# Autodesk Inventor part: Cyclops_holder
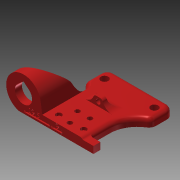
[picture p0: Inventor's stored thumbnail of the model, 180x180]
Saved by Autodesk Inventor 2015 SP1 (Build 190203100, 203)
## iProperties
Created: 2015-09
Part Number: Cyclops_holder
Material: Generic
Document SubType Name: Modeling
Designer: egor
Density: 1 g/cm^3
Appearance: Default
Author: egor
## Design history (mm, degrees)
sketch "Sketch1"
  geometry: L1 (-15, 26.5)-(15, 26.5); L2 (15, 26.5)-(15, -26.5); L3 (15, -26.5)-(-15, -26.5); L4 (-15, -26.5)-(-15, 26.5); L5 (15, -26.5)-(22, -26.5); L6 (22, -26.5)-(22, -21.5); L7 (22, -21.5)-(15, -21.5); L8 (15, -21.5)-(15, -26.5); L9 (15, 26.5)-(27, 26.5); L10 (27, 26.5)-(27, 10.5); L11 (27, 10.5)-(15, 10.5); L12 (15, 10.5)-(15, 26.5); L13 (-15, 26.5)-(-21, 26.5); L14 (-21, 26.5)-(-21, 10.5); L15 (-21, 10.5)-(-15, 10.5); L16 (-15, 10.5)-(-15, 26.5); C1 r 1.7 at (-4.5, -11.5); C2 r 1.7 at (4.5, -11.5); C3 r 1.7 at (0, -21.5); C4 r 2.7 at (-15, 18.5); C5 r 2.7 at (21, 18.5); 5 further points
  constraints: 32 end point, 8 parallel, 5 centre point, 4 horizontal, 4 horizontal alignment, 4 midpoint, 4 perpendicular, 3 equal radius, 2 vertical alignment, 1 coincident, 1 collinear
  dimensions: "d0" = 30 distance of L2.end L3.end; "d3" = 3.4 diameter of C3; "d6" = 9 distance of C2.centre C1.centre; "d7" = 4.5 horizontal distance of point (0, 0) C2.centre; "d8" = 10 vertical distance of C3.centre C2.centre; "d9" = 5 distance from line of L3 C3.centre; "d10" = 7 distance of L7.end L6.end; "d11" = 5 distance between parallel lines of L5 L7; "d12" = 16 distance of L9.end L10.end; "d14" = 5.4 diameter of C4; "d15" = 6 distance from line of L14 C4.centre; "d17" = 6 distance from line of L12 C5.centre; "d18" = 6 distance from line of L10 C5.centre; "d48" = 40 vertical distance of C3.centre C5.centre; "d110" = 30 distance from line of L2 C4.centre
extrude "Base" new body sketch "Sketch1" distance "d19" = 6; taper "d20" = 0 deg
sketch "Sketch2"
  geometry: L1 (0, 6)-(37, 6) reference; L2 (0, 0)-(0, 6) reference; L3 (0, 0)-(-17, 0); L4 (42, 0)-(-6, 0) reference; L5 (0, 6)-(-2.534, 6); L6 (0, 6)-(-1.129, 13.793); L7 (-13.5, 20.094)-(-17.485, 16.749); L8 (-13.5, 20.094)-(-9.515, 16.749); A1 r 12.5 centre (-13.5, 12) between (-10, 0) and (-17, 0); A2 r 6.2 centre (-13.5, 12) between (-17.485, 16.749) and (-9.515, 16.749); 1 further point
  constraints: 10 end point, 6 point on circle, 3 tangent, 2 centre point, 2 collinear, 1 coincident, 1 point on line, 1 vertical alignment
  dimensions: "d21" = 25 diameter of A1; "d23" = 12.4 diameter of A2; "d24" = 1 distance edge to line of A1 L2; "d25" = 6 distance from line of L1 A1.centre; "d28" = 100 deg angle of L8 L7
extrude "Sensor holder" join sketch "Sketch2" distance "d40" = 5; taper "d41" = 0 deg
fillet "Sensor enforcement" dims "d42" = 25
extrude "sensor hole" cut sketch "Sketch2" stored distance "d43" = 5; taper "d44" = 0 deg
sketch "Sketch3"
  geometry: L1 (-13.5, -1.954)-(-4.8, -6.977); L2 (-4.8, -6.977)-(-4.8, -17.023); L3 (-4.8, -17.023)-(-13.5, -22.046); L4 (-13.5, -22.046)-(-22.2, -17.023); L5 (-22.2, -17.023)-(-22.2, -6.977); L6 (-22.2, -6.977)-(-13.5, -1.954); A1 r 6.2 centre (-13.5, -12) between (-9.515, -16.749) and (-17.485, -16.749) reference; 2 further points
  constraints: 12 end point, 1 coincident, 13 other
  dimensions: "d45" = 17.4 distance between parallel lines of L2 L5
extrude "Sensor nut" cut sketch "Sketch3" stored distance "d46" = 0; taper "d47" = 0 deg; dims "d0" = 30, "d3" = 3.4, "d6" = 9, "d7" = 4.5, "d8" = 10, "d9" = 5, "d10" = 7, "d11" = 5, "d12" = 16, "d14" = 5.4, "d15" = 6, "d17" = 6, "d18" = 6, "d48" = 40, "d110" = 30
fillet "horizontal enforcement" dims "d49" = 20
sketch "Sketch4"
  geometry: L1 (-3, 1.9)-(3, 1.9); L2 (3, 1.9)-(3, -1.1); L3 (3, -1.1)-(-3, -1.1); L4 (-3, -1.1)-(-3, 1.9); C1 r 2 at (-9, -20.5); C2 r 2 at (9, -20.5); C3 r 1.7 at (0, -21.5) reference; 2 further points
  constraints: 8 end point, 2 centre point, 2 parallel, 1 equal radius, 1 horizontal, 1 horizontal alignment, 1 midpoint, 1 perpendicular, 1 vertical alignment
  dimensions: "d50" = 4 diameter of C1; "d51" = 18 distance of C2.centre C1.centre; "d54" = 1 vertical distance of C3.centre C2.centre; "d55" = 9 horizontal distance of C2.centre C3.centre (= 0.5 x d51); "d58" = 6 distance of L2.end L3.end; "d59" = 3 distance of L1.end L2.end; "d60" = 20.4 distance from line of L3 C3.centre
extrude "space for bolts" cut sketch "Sketch4" distance "d56" = 2; taper "d57" = 0 deg
extrude "upper fixator" join sketch "Sketch4" distance "d61" = 6; taper "d62" = 0 deg
fillet "upper fixator enforcement" dims "d63" = 7
sketch "Sketch7"
  geometry: L1 (0, 5)-(-6, 5) reference; L2 (-6, 0)-(-5, 0); L3 (-5, 0)-(-5, 5); L4 (-5, 5)-(-6, 5); L5 (-6, 5)-(-6, 0); 1 further point
  constraints: 8 end point, 2 parallel, 1 horizontal, 1 perpendicular, 1 point on line
  dimensions: "d72" = 1 distance of L4.end L3.end
extrude "arm for support" cut sketch "Sketch7" stored distance "d73" = 10; taper "d74" = 0 deg
fillet "Fillet9" dims "d90" = 5
fillet "Fillet10" dims "d91" = 3
fillet "Fillet11" dims "d92" = 2
sketch "Sketch5"
  geometry: L1 (-5.072, 0)-(31.928, 0) reference; C1 r 1.7 at (9.928, 3); 1 further point
  constraints: 1 centre point
  dimensions: "d64" = 3.4 diameter of C1; "d65" = 3 distance from line of L1 C1.centre
extrude "upper fixator hole" cut sketch "Sketch5" stored distance "d66" = 6; taper "d67" = 0 deg; dims "d0" = 30, "d3" = 3.4, "d6" = 9, "d7" = 4.5, "d8" = 10, "d9" = 5, "d10" = 7, "d11" = 5, "d12" = 16, "d14" = 5.4, "d15" = 6, "d17" = 6, "d18" = 6, "d48" = 40, "d110" = 30
sketch "Sketch9"
  geometry: C1 r 1.7 at (3.175, 2) reference; C2 r 2.9 at (3.175, 2); 2 further points
  constraints: 1 centre point, 1 coincident, 1 other
  dimensions: "d93" = 5.8 diameter of C2
extrude "embedded bolt" cut sketch "Sketch9" stored distance "d94" = 1; taper "d95" = 0 deg; dims "d0" = 30, "d3" = 3.4, "d6" = 9, "d7" = 4.5, "d8" = 10, "d9" = 5, "d10" = 7, "d11" = 5, "d12" = 16, "d14" = 5.4, "d15" = 6, "d17" = 6, "d18" = 6, "d48" = 40, "d110" = 30
sketch "Sketch10"
  geometry: L1 (4.914, 1.3)-(21.586, 1.3); L2 (21.586, 0.386)-(21.586, 3.214); L3 (21.586, 2.3)-(4.914, 2.3); L4 (4.914, 3.214)-(4.914, 0.386); L5 (21.586, 3.214)-(23, 1.8); L6 (23, 1.8)-(21.586, 0.386); L7 (4.914, 3.214)-(3.5, 1.8); L8 (3.5, 1.8)-(4.914, 0.386); L9 (6.82, 5.8)-(15.992, 5.8); L10 (15.992, 5.8)-(15.992, 2.058); L11 (15.992, 2.058)-(6.82, 2.058); L12 (6.82, 2.058)-(6.82, 5.8); L13 (24.414, 1.3)-(30.586, 1.3); L14 (30.586, 2.3)-(24.414, 2.3); L15 (16.992, 3.144)-(7.82, 3.144); L16 (24.414, 3.214)-(24.414, 0.386); L17 (23, 1.8)-(24.414, 0.386); L18 (24.414, 3.214)-(23, 1.8); L19 (30.586, 0.386)-(30.586, 3.214); L20 (30.586, 3.214)-(32, 1.8); L21 (32, 1.8)-(30.586, 0.386); L22 (26.655, 2.018)-(26.655, 5.8); L23 (26.655, 5.8)-(30.117, 5.8); L24 (30.117, 5.8)-(30.117, 2.018); L25 (30.117, 2.018)-(26.655, 2.018); A1 r 6.2 centre (3.5, 12) between (-0.485, 16.749) and (7.485, 16.749) reference; 1 further point
  constraints: 32 end point, 10 perpendicular, 9 vertical alignment, 8 point on line, 4 horizontal alignment, 4 parallel, 2 horizontal, 1 collinear, 4 other
  dimensions: "d98" = 1 distance between parallel lines of L1 L3; "d99" = 0.5 distance from line of L3 L5.end (= 0.5 x d98); "d100" = 2 distance of L2.end L5.end; "d101" = 19.5 distance of L5.end L7.end; "d102" = 1.8 vertical distance of point (32, 0) L5.end; "d103" = 1 distance between parallel lines of L13 L14; "d104" = 0.5 distance from line of L14 L20.end (= 0.5 x d103); "d105" = 2 distance of L19.end L20.end; "d106" = 9 distance of L5.end L20.end; "d107" = 3.5 distance between parallel lines of L14 L23
extrude "Extrusion14" cut sketch "Sketch10" distance "d108" = 1; taper "d109" = 0 deg
body "Solid1"
node "Projected Loop2"
